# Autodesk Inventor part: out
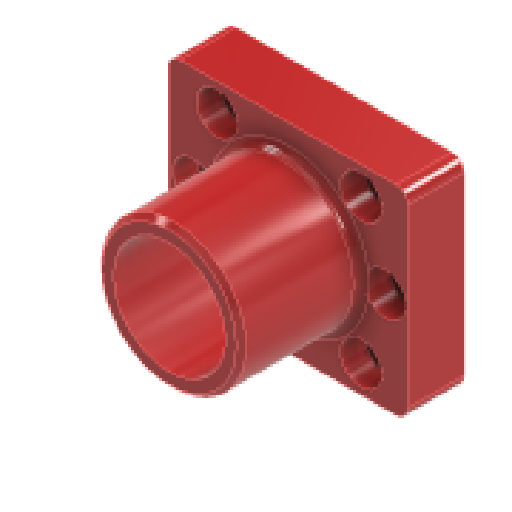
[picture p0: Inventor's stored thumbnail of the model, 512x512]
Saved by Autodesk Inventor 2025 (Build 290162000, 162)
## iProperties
Created: 2025-04
Part Number: out
Material: Plastica PET
Document SubType Name: Modeling
Designer: R5800u
Density: 1.541 g/cm^3
Appearance: Rosso
Author: R5800u
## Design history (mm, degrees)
sketch "Schizzo1"
  geometry: L1 (6.503, 2.5)-(0, 2.5) reference; L2 (0, -11)-(0, 2.5) reference; L3 (28.5, -12.5)-(1.5, -12.5) reference; L4 (30, -11)-(30, 2.5) reference; L5 (30, 2.5)-(23.795, 2.5) reference; L6 (0, 2.5)-(6.503, 2.5) reference; L7 (23.795, 2.5)-(30, 2.5) reference; L8 (30, 2.5)-(30, 11) reference; L9 (1.5, 12.5)-(28.5, 12.5) reference; L10 (0, 2.5)-(0, 11) reference; L11 (3.149, 0)-(27.149, 0); C1 r 1.325 at (27.149, 0) reference; C2 r 1.325 at (24.164, -9.019) reference; C3 r 1.325 at (6.135, -9.019) reference; C4 r 1.325 at (3.149, 0) reference; C5 r 1.325 at (6.135, 9.019) reference; C6 r 1.325 at (24.164, 9.019) reference; C7 r 9 at (15.149, 0); C8 r 7 at (15.149, 0); A1 r 1.5 centre (1.5, -11) between (0, -11) and (1.5, -12.5) reference; A2 r 1.5 centre (28.5, -11) between (28.5, -12.5) and (30, -11) reference; A3 r 1.5 centre (28.5, 11) between (30, 11) and (28.5, 12.5) reference; A4 r 1.5 centre (1.5, 11) between (1.5, 12.5) and (0, 11) reference; 5 further points
  constraints: 2 centre point, 2 end point, 1 coincident, 1 horizontal, 1 midpoint, 1 other
  dimensions: "d0" = 18 diameter of C7; "d1" = 14 diameter of C8
extrude "Estrusione1" new body sketch "Schizzo1" distance "d2" = 7; taper "d3" = 0 deg
sketch "Schizzo2"
  geometry: C1 r 7 at (15.149, 0) reference; C2 r 9 at (15.149, 0); 1 further point
  constraints: 1 centre point, 1 coincident
  dimensions: "d4" = 18 diameter of C2
extrude "Estrusione2" join sketch "Schizzo2" distance "d5" = 15; taper "d6" = 0 deg
fillet "Raccordo1" dims "d7" = 1
sketch "Schizzo3"
  geometry: C1 r 7 at (-15.149, 0) reference; C2 r 7 at (-15.149, 0); C3 r 10 at (-15.149, 0); 1 further point
  constraints: 2 centre point, 2 coincident
  dimensions: "d8" = 20 diameter of C3
extrude "Estrusione3" cut sketch "Schizzo3" distance "d9" = 2; taper "d10" = 0 deg
chamfer "Smusso1" distance "d12" = 0.6; stored, may be unused: second distance "d13" = 2, angle "d14" = 45 deg
sketch "Schizzo4"
  geometry: C1 r 1.325 at (6.135, 9.019) reference; C2 r 1.325 at (3.149, 0) reference; C3 r 1.325 at (6.135, -9.019) reference; C4 r 1.325 at (24.164, -9.019) reference; C5 r 1.325 at (27.149, 0) reference; C6 r 1.325 at (24.164, 9.019) reference; 7 further points
  constraints: 6 coincident
hole "Foro1" sketch "Schizzo4" at (6.135, 9.019), (3.149, 0), (6.135, -9.019), (24.164, -9.019), (27.149, 0), (24.164, 9.019) diameter "d15" = 2.5; stored, may be unused: countersink angle "d19" = 90 deg, drill point angle "d21" = 118 deg; dims "d16" = 6, "d17" = 5.2, "d18" = 3, "d20" = 8
node "Solido1"
node "Riferimento1"
node "Riferimento2"
